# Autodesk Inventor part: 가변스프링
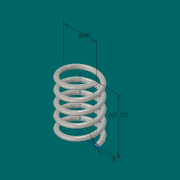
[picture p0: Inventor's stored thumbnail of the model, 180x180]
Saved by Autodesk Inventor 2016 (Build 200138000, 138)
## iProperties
Created: 2018-08
Part Number: 가변스프링
Material: 스테인레스 스틸
Document SubType Name: Modeling
Designer: 605-04
Density: 8 g/cm^3
Appearance: 반연마
Mass: 97.137 g
Surface Area: 98.6596 cm^2
Volume: 12.1421 cm^3
Author: 605-04
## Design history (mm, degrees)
sketch "스케치1"
  geometry: L1 (0, 0)-(20, 0); L2 (20, 0)-(20, 67.25); L3 (20, 67.25)-(0, 67.25); L4 (0, 67.25)-(0, 0); C1 r 2.5 at (20, 0)
  constraints: 8 end point, 2 parallel, 1 centre point, 1 coincident, 1 horizontal, 1 perpendicular
  dimensions: "d0" = 67.25 distance of L1.end L2.end (derived); "d1" = 40 diameter of L2 L4; "d2" = 5 diameter of C1
feature "코일1" pitch "d3" = 10; turns "d5" = 5; dims "d4" = 67.25 (= d0), "d6" = 0, angle "d7" = 90 deg, angle "d8" = 90 deg, "d9" = 0, "d10" = 0
sketch "스케치2"
  geometry: L1 (-22.5, 0)-(-17.5, 0) reference; 1 further point
  constraints: 1 horizontal alignment
extrude "돌출1" cut sketch "스케치2" stored distance "d11" = 10; taper "d12" = 0 deg
node "작업 평면1"
sketch "스케치3"
  geometry: L1 (2.5, 0)-(-2.5, 0) reference; 1 further point
  constraints: 1 horizontal alignment
extrude "돌출2" cut sketch "스케치3" stored distance "d14" = 10; taper "d15" = 0 deg
node "솔리드1"
node "절단 모서리 투영1"
node "절단 모서리 투영2"
other parameters: "d13" = 90 deg
